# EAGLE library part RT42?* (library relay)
Power PCB Relay SCHRACK 2 pole 8 A, DC and AC-coil Source: http://www.schrack.com/.. 5842.pdf
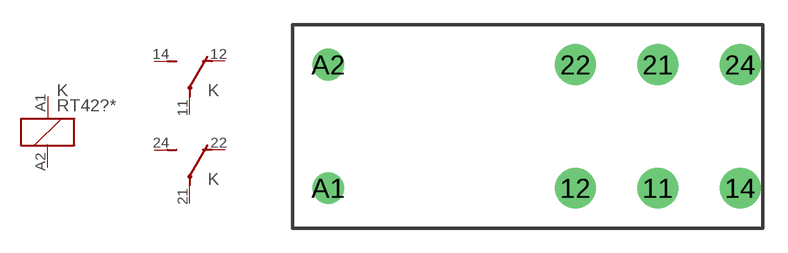
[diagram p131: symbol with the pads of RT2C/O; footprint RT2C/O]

Designator prefix K; gates 1=K 2=U 3=U

## RT424005 (MPN: RT424005; OC_FARNELL: 1629052; OC_NEWARK: 03P2425), RT424006 (MF: TYCO ELECTRONICS; MPN: RT424006; OC_FARNELL: unknown; OC_NEWARK: 08H3752), RT424012 (MPN: RT424012; OC_FARNELL: 1629053; OC_NEWARK: 03P2426), RT424024 (MF: TYCO ELECTRONICS; MPN: RT424024; OC_FARNELL: 1629054; OC_NEWARK: 16F393), RT424048 (MPN: RT424048; OC_FARNELL: 1629055; OC_NEWARK: 03P2428), RT424060 (OC_FARNELL: unknown; OC_NEWARK: unknown), RT424110 (MPN: RT424110; OC_FARNELL: unknown; OC_NEWARK: 93B6583), RT424524 (MF: TYCO ELECTRONICS; MPN: RT424524; OC_FARNELL: 1629056; OC_NEWARK: 94C4293), RT424615 (MF: TYCO ELECTRONICS; MPN: RT424615; OC_FARNELL: 1629057; OC_NEWARK: 48F1292), RT424730 (MF: TYCO ELECTRONICS; MPN: RT424730; OC_FARNELL: 1629058; OC_NEWARK: 85C0866)  [RT2C/O]
11  2:P  pas
12  2:O  pas
14  2:S  pas
21  3:P  pas
22  3:O  pas
24  3:S  pas
A1  1:1  pas
A2  1:2  pas

## RT425005 (MF: TYCO ELECTRONICS; MPN: 8-1393243-0; OC_FARNELL: unknown; OC_NEWARK: 16H6457), RT425006 (OC_FARNELL: unknown; OC_NEWARK: unknown), RT425012 (MF: TYCO ELECTRONICS; MPN: 8-1393243-2; OC_FARNELL: unknown; OC_NEWARK: 16H6458), RT425024 (MF: TYCO ELECTRONICS; MPN: 8-1393243-5; OC_FARNELL: unknown; OC_NEWARK: 16H6459), RT425048 (OC_FARNELL: unknown; OC_NEWARK: unknown), RT425060 (OC_FARNELL: unknown; OC_NEWARK: unknown), RT425110 (OC_FARNELL: unknown; OC_NEWARK: unknown), RT425524 (MPN: RT425524; OC_FARNELL: unknown; OC_NEWARK: 48M7992), RT425615 (MPN: RT425615; OC_FARNELL: unknown; OC_NEWARK: 48M7993), RT425730 (MF: TYCO ELECTRONICS; MPN: 9-1393243-3; OC_FARNELL: unknown; OC_NEWARK: 83H4419)  [RT2C/O]
11  3:P  pas
12  3:O  pas
14  3:S  pas
21  2:P  pas
22  2:O  pas
24  2:S  pas
A1  1:1  pas
A2  1:2  pas

## Footprint RT2C/O (pad centres in mm)
Power PCB Relay DC and AC-coil SCHRACK 2 pole 8 A Source: http://www.schrack.com/.. 5842.pdf
drill 1.3 pad 2.5 round: 11 7.56,-3.68; 12 2.52,-3.68; 14 12.6,-3.68; 21 7.56,3.88; 22 2.52,3.88; 24 12.6,3.88
drill 1.3 round: A1 -12.6,-3.68; A2 -12.6,3.88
